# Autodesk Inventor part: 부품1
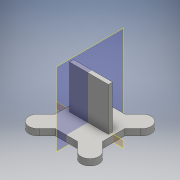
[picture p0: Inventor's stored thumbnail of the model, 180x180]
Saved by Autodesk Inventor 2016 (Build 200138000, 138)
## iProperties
Created: 2017-03
Part Number: 부품1
Material: 일반
Document SubType Name: Modeling
Designer: USER
Density: 1 g/cm^3
Appearance: 기본값
Author: USER
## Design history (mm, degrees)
sketch "스케치1"
  geometry: L1 (0, 0)-(70, 0); L2 (0, 0)-(70, 0); L3 (45, 21.136)-(45, -21.136); L4 (21.136, -45)-(-21.136, -45); L5 (-36.106, -59.97)-(-21.136, -45); L6 (-36.106, -59.97)-(-14.936, -59.97); L7 (-59.97, -36.106)-(-45, -21.136); L8 (-59.97, -36.106)-(-38.799, -36.106); L9 (-59.97, 36.106)-(-45, 21.136); L10 (-59.97, 36.106)-(-39.025, 36.106); L11 (-36.106, 59.97)-(-21.136, 45); L12 (-36.106, 59.97)-(-14.936, 59.97); L13 (36.106, 59.97)-(21.136, 45); L14 (36.106, 59.97)-(57.276, 59.97); L15 (59.97, 36.106)-(45, 21.136); L16 (59.97, 36.106)-(81.14, 36.106); L17 (36.106, -59.97)-(21.136, -45); L18 (36.106, -59.97)-(57.276, -59.97); L19 (59.97, -36.106)-(45, -21.136); L20 (59.97, -36.106)-(81.14, -36.106); L21 (45, -45)-(37.477, -37.477); L22 (0, 0)-(-45, 45); L23 (45, 45)-(37.477, 37.477); L24 (-45, -21.136)-(-45, 21.136); L25 (-21.136, 45)-(21.136, 45); A1 r 17 centre (49.497, 49.497) between (59.97, 36.106) and (36.106, 59.97); A2 r 17 centre (-49.497, -49.497) between (-59.97, -36.106) and (-36.106, -59.97); A3 r 17 centre (49.497, -49.497) between (36.106, -59.97) and (59.97, -36.106); A4 r 17 centre (-49.497, 49.497) between (-36.106, 59.97) and (-59.97, 36.106)
  constraints: 50 end point, 10 horizontal, 8 point on circle, 7 equal length, 4 centre point, 2 parallel, 1 perpendicular, 1 vertical
  dimensions: "d120" = 34 diameter of A1; "d123" = 45 deg angle of L6 L5; "d124" = 45 deg angle of L8 L7; "d125" = 45 deg angle of L9 L10; "d126" = 45 deg angle of L11 L12; "d127" = 135 deg angle of L13 L14; "d128" = 135 deg angle of L15 L16; "d129" = 135 deg angle of L18 L17; "d130" = 135 deg angle of L20 L19
extrude "돌출1" new body sketch "스케치1" distance "d15" = 12; taper "d16" = 0 deg
sketch "스케치2"
  geometry: L1 (-35, 4)-(39, 4); L2 (39, 4)-(39, -4); L3 (39, -4)-(-35, -4); L4 (-35, -4)-(-35, 4); 1 further point
  constraints: 8 end point, 2 parallel, 1 horizontal, 1 perpendicular
  dimensions: "d18" = 4 distance from line of point (0, 0) L1; "d88" = 74 distance of L1.start L1.end; "d89" = 35 distance from line of point (0, 0) L4; "d90" = 4 distance from line of L3 point (0, 0)
node "작업 평면1"
sketch "스케치3"
  geometry: L1 (-16.999, 82)-(83.001, 82); L2 (-16.999, 82)-(-16.999, 127); L3 (-16.999, 127)-(3.001, 127); L4 (3.001, 127)-(14.001, 118); L5 (14.001, 118)-(48.001, 118); L6 (48.001, 118)-(60.001, 109.5); L7 (60.001, 109.5)-(83.001, 109.5); L8 (83.001, 109.5)-(83.001, 82); L9 (66.003, 0)-(0, 0) reference; L10 (66.003, 12)-(0, 12) reference; 1 further point
  constraints: 16 end point, 2 horizontal, 2 perpendicular, 1 parallel, 1 vertical
  dimensions: "d19" = 90 diameter of L3 L1; "d20" = 72 diameter of L5 L1; "d21" = 55 diameter of L7 L1; "d22" = 82 distance between parallel lines of L9 L1; "d23" = 20 distance of L2.end L3.end; "d24" = 31 horizontal distance of L4.end L2.end; "d25" = 65 horizontal distance of L2.end L5.end; "d26" = 100 distance between parallel lines of L8 L2; "d27" = 23 distance of L6.end L7.end
revolve "회전1" sketch "스케치3" stored, may be unused: angle "d29" = 90 deg
sketch "스케치4"
  geometry: L1 (33.001, 0)-(33.001, 122); L2 (83.001, 54.5)-(83.001, 109.5) reference; L3 (83.001, 82)-(23.823, 82); L4 (14.001, 118)-(48.001, 118) reference; L5 (33.001, 122)-(28.001, 122); L6 (28.001, 122)-(28.001, 112); L7 (28.001, 112)-(33.001, 112)
  constraints: 10 end point, 2 horizontal, 2 perpendicular, 1 midpoint, 1 point on line, 1 vertical
  dimensions: "d30" = 40 distance between parallel lines of L3 L5; "d31" = 5 distance of L1.end L5.end; "d32" = 10 distance between parallel lines of L5 L7
revolve "회전2" sketch "스케치4" stored, may be unused: angle "d33" = 90 deg
sketch "스케치6"
  geometry: 2 further points
hole "구멍1" sketch "스케치6" at (40, 0) diameter "d41" = 3.242; stored, may be unused: countersink angle "d45" = 90 deg, drill point angle "d47" = 118 deg; dims "d42" = 9, "d43" = 4, "d44" = 2, "d46" = 11
sketch "스케치7"
  geometry: L1 (60.001, 109.5)-(83.001, 109.5) reference; L2 (83.001, 54.5)-(83.001, 109.5) reference; L3 (83.001, 109.5)-(83.001, 116.5); L4 (83.001, 116.5)-(68.001, 116.5); L5 (68.001, 116.5)-(68.001, 109.5); L6 (68.001, 109.5)-(83.001, 109.5); 1 further point
  constraints: 8 end point, 3 perpendicular, 2 point on line
  dimensions: "d51" = 7 distance of L3.start L3.end; "d52" = 15 distance of L3.end L4.end; "d53" = 0 distance between parallel lines of L1 L6
revolve "회전4" sketch "스케치7" stored, may be unused: angle "d54" = 90 deg
sketch "스케치8"
  geometry: A1 r 27.5 centre (27.5, 0) between (34.792, 26.516) and (0.891, 6.943) reference; A2 r 7 centre (0, 0) between (0.891, 6.943) and (0.891, -6.943) reference; A3 r 27.5 centre (27.5, 0) between (0.891, -6.943) and (34.792, -26.516) reference; A4 r 7 centre (41.25, -23.816) between (34.792, -26.516) and (46.817, -19.573) reference; A5 r 27.5 centre (27.5, 0) between (46.817, -19.573) and (46.817, 19.573) reference; A6 r 7 centre (41.25, 23.816) between (46.817, 19.573) and (34.792, 26.516) reference; 2 further points
  constraints: 1 coincident
hole "구멍2" sketch "스케치8" at (0, 0) diameter "d60" = 3.242; stored, may be unused: countersink angle "d64" = 90 deg, drill point angle "d66" = 118 deg; dims "d61" = 9, "d62" = 4, "d63" = 2, "d65" = 11
fillet "모깎기4" dims "d86" = 3
fillet "모깎기5" dims "d87" = 1
extrude "돌출2" join sketch "스케치2" distance "d91" = 82; taper "d92" = 0 deg
node "작업 평면2"
sketch "스케치10"
  geometry: L1 (0, 0)-(0, 66.003) reference; L2 (0, 0)-(12, 0) reference; L3 (12, 66.003)-(12, 0) reference; L4 (0, 66.003)-(12, 66.003) reference; L5 (0, -10.132)-(0, 0) reference; L6 (0, -10.132)-(12, -10.132) reference; L7 (12, 0)-(12, -10.132) reference; L8 (0, 0)-(12, 0) reference; L9 (0, 66.003)-(0, 76.135) reference; L10 (0, 66.003)-(12, 66.003) reference; L11 (12, 76.135)-(12, 66.003) reference; L12 (0, 76.135)-(12, 76.135) reference; L13 (12, 66.003)-(12, 0) reference; L14 (12, 33.001)-(12, 8.001); L15 (12, 8.001)-(82, 20.344); L16 (12, 33.001)-(12, 58.001); L17 (12, 58.001)-(82, 45.658); L18 (82, 45.658)-(82, 20.344); 1 further point
  constraints: 10 end point, 2 point on line, 1 midpoint, 1 parallel
  dimensions: "d93" = 25 distance of L14.start L14.end; "d94" = 80 deg angle of L15 L14; "d95" = 25 distance of L14.start L16.end; "d96" = 80 deg angle of L16 L17; "d97" = 82 distance between parallel lines of L1 L18
extrude "돌출3" join sketch "스케치10" stored distance "d98" = 8; taper "d99" = 0 deg
sketch "스케치11"
  geometry: 1 further point
sketch "스케치12"
  geometry: L1 (72.001, 54.792)-(60.001, 54.792) reference; L2 (60.001, 54.792)-(60.001, 54.792) reference; L3 (60.001, 54.792)-(72.001, 54.792) reference; L4 (72.001, 54.792)-(72.001, 54.792) reference; L5 (83.001, 62.119)-(71.001, 62.119) reference; L6 (83.001, 62.119)-(83.001, 62.119) reference; L7 (71.001, 62.119)-(83.001, 62.119) reference; L8 (67.001, 71.668)-(67.001, 65.095) reference; L9 (83.001, 108.395)-(71.001, 75.487) reference; L10 (83.001, 108.395)-(83.001, 108.395) reference; L11 (71.001, 108.395)-(83.001, 108.395) reference; L12 (67.001, 109.237)-(67.001, 109.237) reference; L13 (83.001, 108.395)-(71.001, 108.395) reference; L14 (83.001, 75.487)-(83.001, 108.395) reference; L15 (71.001, 75.487)-(83.001, 75.487) reference; L16 (67.001, 65.095)-(67.001, 71.668) reference; L17 (48.001, 46.223)-(48.001, 46.223) reference; L18 (60.001, 54.792)-(60.001, 54.792) reference; L19 (14.001, 118)-(48.001, 118) reference; L20 (-16.999, 127)-(3.001, 127) reference; L21 (-16.999, 37)-(-16.999, 127) reference; L22 (66.003, 0)-(0, 0) reference; L23 (-16.999, 82)-(83.001, 82); L24 (83.001, 108.395)-(83.001, 108.395) reference; L25 (83.001, 82)-(83.001, 99.5); L26 (83.001, 99.5)-(53.001, 99.5); L27 (53.001, 99.5)-(53.001, 108); L28 (53.001, 108)-(6.001, 108); L29 (6.001, 108)-(6.001, 117); L30 (6.001, 117)-(-16.999, 117); 1 further point
  constraints: 14 end point, 5 perpendicular, 3 point on line, 1 horizontal, 1 midpoint, 8 other
  dimensions: "d100" = 23 distance of L29.end L30.end; "d101" = 47 distance of L27.end L28.end; "d102" = 70 diameter of L30 L23; "d103" = 52 diameter of L28 L23; "d104" = 35 diameter of L26 L23
revolve "회전5" sketch "스케치12" stored, may be unused: angle "d105" = 90 deg
fillet "모깎기6" dims "d106" = 3
chamfer "모따기3" distance "d107" = 1; stored, may be unused: second distance "d108" = 2, angle "d109" = 45 deg
fillet "모깎기7" dims "d113" = 25
node "솔리드1"
pattern_circular "원형 패턴1" dims angle "d49" = 360 deg
pattern_circular "원형 패턴2" dims angle "d56" = 360 deg
pattern_circular "원형 패턴4" dims angle "d111" = 360 deg
node "투영된 루프1"
node "투영된 루프2"
node "투영된 루프3"
node "투영된 루프4"
node "투영된 루프5"
node "투영된 루프6"
other parameters: "d3" = 45, "d4" = 45, "d6" = 17, "d7" = 17, "d8" = 17, "d9" = 17, "d117" = 34, "d118" = 34, "d119" = 34
